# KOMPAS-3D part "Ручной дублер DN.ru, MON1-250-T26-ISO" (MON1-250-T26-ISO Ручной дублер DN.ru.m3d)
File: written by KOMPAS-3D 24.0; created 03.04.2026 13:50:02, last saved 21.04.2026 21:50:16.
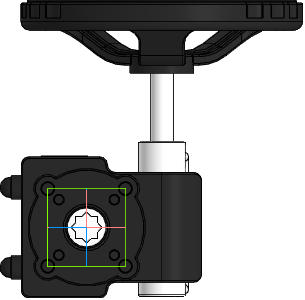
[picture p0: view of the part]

Document properties: Автор: R2D2; Полное имя файла: MON1-250-T26-ISO Ручной дублер DN.ru.cdw

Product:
- Part/product: Ручной дублер DN.ru  | designation MON1-250-T26-ISO
    Масса: 3
    Раздел спецификации: Прочие изделия
    Форматы листов документа: A2
    Примечание: D290-00336

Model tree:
1. Операция без истории:2

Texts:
  MON1-250-T26-ISO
